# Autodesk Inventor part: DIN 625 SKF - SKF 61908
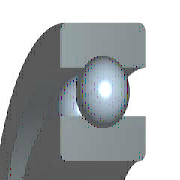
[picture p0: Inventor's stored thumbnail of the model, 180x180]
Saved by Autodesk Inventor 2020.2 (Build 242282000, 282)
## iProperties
Manager: www.cadconsulting.pl
Company: Fabian Stasiak CAD Consulting
Created: 2010-02
Part Number: DIN 625 SKF - SKF 61908
Material: Stal, miękka
Description: Łożyska kulkowe jednorzędowe
Document SubType Name: Modeling
Standard: DIN 625
Designer: F.Stasiak
Standards Organization: DIN
Language: pl-PL
Size Designation: SKF 61908
Categories: <MemberInstance><Categories><Category DisplayName="Części wałów" InternalName="7f7aeb1f-a693-4053-b835-cee3144e0d98" Mnemonic="SHFT"><Category DisplayName="Łoży
Density: 7.86 g/cm^3
Appearance: Metal-Stal
IsCustomPart: 0
Author: F.Stasiak
Subject: Zbiór ćwiczeń. Autodesk Inventor 2020. Kurs podstawowy
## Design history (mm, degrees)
node "Sketch1"
node "WorkPoint1"
sketch "Sketch2"
  geometry: L1 (20, 12)-(31, 12); L2 (20, 0)-(20, 12); L3 (31, 0)-(20, 0); L4 (31, 12)-(31, 0); L5 (0, 0)-(0, 20); L6 (0, 0)-(0, 20); L7 (-7.2, 0)-(43.2, 0) reference
  constraints: 12 end point, 3 vertical, 2 horizontal, 1 collinear, 1 other
  dimensions: "d1" = 40 diameter of L1.start L5 (= Diam); "d3" = 62 diameter of L1.end L5 (= DD); "d5" = 12 distance of L2.start L1.start (= msp_mdtd2)
revolve "Revolution1" sketch "Sketch2" stored, may be unused: angle "d6" = 360 deg
node "WorkAxis1"
node "WorkPlane3"
sketch "Sketch3"
  geometry: L1 (27.48, 12)-(27.48, 8.64); L2 (23.52, 12)-(27.48, 12); L3 (23.52, 8.64)-(23.52, 12); L4 (23.52, 0)-(23.52, 3.36); L5 (27.48, 0)-(23.52, 0); L6 (27.48, 3.36)-(27.48, 0); L7 (31, 0)-(-31, 0) reference; L8 (31, 12)-(-31, 12) reference; L9 (0, -42.29)-(0, 61.29); L10 (0, 82.007)-(0, -63.007) reference; A1 r 3.3 centre (25.5, 6) between (27.48, 3.36) and (27.48, 8.64); A2 r 3.3 centre (25.5, 6) between (23.52, 8.64) and (23.52, 3.36)
  constraints: 14 end point, 4 collinear, 4 point on circle, 4 vertical, 2 centre point, 2 concentric, 2 horizontal, 2 point on line
  dimensions: "d9" = 6.6 diameter of A1 (= msp_mdtd6); "d21" = 23.52 distance between parallel lines of L9 L4 (= 0.5 x msp_d1); "d22" = 25.5 distance from line of L9 A1.centre (= 0.5 x msp_ds); "d23" = 27.48 distance between parallel lines of L9 L6 (= 0.5 x msp_dd1)
revolve "Revolution2" sketch "Sketch3" stored, may be unused: angle "d10" = 360 deg
node "WorkPlane4"
node "Sketch4"
node "WorkPoint2"
revolve "Revolution3" stored, may be unused: angle "d16" = 360 deg
pattern_circular "PolarArray1" dims "d17" = 119.90909 (= msp_pocet), angle "d19" = 360 deg
fillet "Fillet1" dims "d20" = 0.6 (= r)
body "Solid1"
sketch "Sketch5"
  geometry: L1 (25.5, 2.7)-(25.5, 9.3); L2 (27.48, 0)-(-27.48, 0) reference; L3 (25.5, 2.7)-(25.5, 9.3); A1 r 3.3 centre (25.5, 6) between (25.5, 2.7) and (25.5, 9.3); A2 r 3.3 centre (25.5, 6) between (27.48, 3.36) and (27.48, 8.64) reference
  constraints: 4 end point, 2 point on circle, 1 centre point, 1 concentric, 1 vertical
  dimensions: "d13" = 0 horizontal distance of A1.centre L1.start; "d15" = 6.6001 diameter of A1 (computed from msp_mdtd6)
other parameters: "Diam" = 40 [user parameter; used in 3 equation terms], "DD" = 62 [user parameter; used in 3 equation terms], "B" = 12 [user parameter; used in 1 equation term], "r" = 0.6 [user parameter; used in 1 equation term], "msp_ds" = 51 (= 0.5 x Diam + 0.5 x DD) [user parameter; used in 5 equation terms], "msp_d0" = 6.6 (= -0.3 x Diam + 0.3 x DD) [user parameter; used in 4 equation terms], "msp_d1" = 47.04 (= msp_ds - 0.6 x msp_d0) [user parameter; used in 1 equation term], "msp_dd1" = 54.96 (= msp_ds + 0.6 x msp_d0) [user parameter; used in 1 equation term], "msp_pom" = 76.5 (= 1.5 x msp_ds) [user parameter; used in 1 equation term], "msp_mdtd2" = 12 (= B) [user parameter; used in 3 equation terms], "msp_mdtd4" = 51 (= msp_ds) [user parameter], "msp_mdtd6" = 6.6 (= msp_d0) [user parameter; used in 2 equation terms], "msp_mdtd7" = 6 (= 0.5 x msp_mdtd2) [user parameter], "msp_pocet" = 119.90909 (computed from msp_d0, msp_pom) [user parameter; used in 1 equation term], "d2" = 72 (derived), "d4" = 19 (derived), "d7" = 0, "d8" = 15.6 (derived), "d11" = -12 (computed from msp_mdtd2), "d12" = 0 (derived), "d14" = 15.6001 (derived), "d26" = 0, "d27" = 0, "d28" = 0, "d29" = 0, "d30" = 0
